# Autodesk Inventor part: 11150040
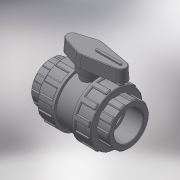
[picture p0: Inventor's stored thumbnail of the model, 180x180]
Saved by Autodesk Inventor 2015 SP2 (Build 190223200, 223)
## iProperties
Created: 2017-11
Part Number: 11150040
Material: Generic
Description: PLASSON 2/NUT VALVE CEM. PVC 40
Document SubType Name: Modeling
Designer: KIM
Density: 1 g/cm^3
Appearance: Default
Author: KIM
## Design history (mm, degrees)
derived "111500.ipt"
feature "Solid1::111500.ipt"
tag "TaggingFeature1"
body "Solid1"
other parameters: "d3" = 26, "d4" = 32, "d5" = 18.2, "d7" = 56, "d8" = 72, "d13" = 1.2, "d23" = 26, "d24" = 76.8, "d25" = 0.8, "d26" = 1.2, "d27" = 12, "d28" = 6, "d29" = 19.5, "d30" = 0, "d35" = 1.2, "d45" = 360 deg, "d47" = 0.8, "d50" = 44, "d51" = 24, "d53" = 0, "d55" = 8, "d56" = 4, "d57" = 18.2, "d58" = 0, "d59" = 1.2, "d61" = 360 deg, "d63" = 32, "d64" = 74, "d66" = 96, "d68" = 16, "d69" = 28.8, "d70" = 18.5, "d71" = 3 deg, "d73" = 1.6, "d74" = 38.4, "d75" = 2.22, "d76" = 0, "d77" = 0.8, "l_" = 26, "F_" = 74, "J_" = 96, "d67" = 32, "d72" = 8
